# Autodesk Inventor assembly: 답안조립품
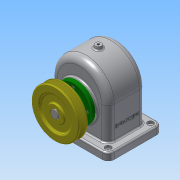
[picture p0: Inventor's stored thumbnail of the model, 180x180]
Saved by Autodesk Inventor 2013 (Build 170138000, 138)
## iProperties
Created: 2016-10
Part Number: 답안조립품
Document SubType Name: Assembly
Designer: Administrator
Author: Administrator
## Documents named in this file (15)
- C:\Users\Administrator\Desktop\461008V1024\답안조립품.iam
- C:\Users\Administrator\Desktop\461008V1024\본체.ipt
- C:\Users\Administrator\Desktop\461008V1024\V-벨트풀리.ipt
- C:\Users\Administrator\Desktop\461008V1024\뒤커버.ipt
- C:\Users\Administrator\Desktop\461008V1024\멈춤나사 - M4x10.ipt
- C:\Users\Administrator\Desktop\461008V1024\베어링 6203.ipt
- C:\Users\Administrator\Desktop\461008V1024\볼트 M3 x 8.ipt
- C:\Users\Administrator\Desktop\461008V1024\볼트 M3 x 10.ipt
- C:\Users\Administrator\Desktop\461008V1024\부시.ipt
- C:\Users\Administrator\Desktop\461008V1024\스퍼기어.ipt
- C:\Users\Administrator\Desktop\461008V1024\앞커버.ipt
- C:\Users\Administrator\Desktop\461008V1024\오일씰 28 40 8.ipt
- C:\Users\Administrator\Desktop\461008V1024\축.ipt
- C:\Users\Administrator\Desktop\461008V1024\키 - 5 x 5 x 18.ipt
- C:\Users\Administrator\Desktop\461008V1024\키 - 6 x 6 x 22.ipt
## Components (9 placed, 3 different names)
1. V-벨트풀리:1
2. ISO 4762 M3 x 8:1
3. ISO 4762 M3 x 8:2
4. ISO 4762 M3 x 8:3
5. ISO 4762 M3 x 8:4
6. ISO 4762 M3 x 10:1
7. ISO 4762 M3 x 10:2
8. ISO 4762 M3 x 10:3
9. ISO 4762 M3 x 10:4
